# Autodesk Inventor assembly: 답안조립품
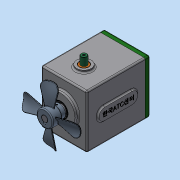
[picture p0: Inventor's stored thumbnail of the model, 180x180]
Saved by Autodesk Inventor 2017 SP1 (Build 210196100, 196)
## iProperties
Part Number: 답안조립품
Material: 일반
Document SubType Name: Assembly
Designer: MRC
Mass: 2669.46 g
Surface Area: 1952.93 cm^2
Volume: 798.897 cm^3
Density: 3.34143 g/cm^3
Author: MRC
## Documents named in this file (17)
- C:\Users\MRC\Desktop\610205V1002\답안조립품.iam
- C:\Users\MRC\Desktop\610205V1002\본체.ipt
- C:\Users\MRC\Desktop\610205V1002\멈춤나사 M3x8.ipt
- C:\Users\MRC\Desktop\610205V1002\메인 기어 축.ipt
- C:\Users\MRC\Desktop\610205V1002\베어링 608.ipt
- C:\Users\MRC\Desktop\610205V1002\베어링 6903.ipt
- C:\Users\MRC\Desktop\610205V1002\볼트 M4 x 10.ipt
- C:\Users\MRC\Desktop\610205V1002\부시.ipt
- C:\Users\MRC\Desktop\610205V1002\서브 기어 축.ipt
- C:\Users\MRC\Desktop\610205V1002\슬라이더.ipt
- C:\Users\MRC\Desktop\610205V1002\오일 실 8 22 7.ipt
- C:\Users\MRC\Desktop\610205V1002\오일 실 17 30 8.ipt
- C:\Users\MRC\Desktop\610205V1002\커버.ipt
- C:\Users\MRC\Desktop\610205V1002\키 5 x 5 x 24.ipt
- C:\Users\MRC\Desktop\610205V1002\팬날개.ipt
- 팬날개.ipt
- C:\Users\MRC\Desktop\610205V1002\가변스프링.ipt
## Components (1 placed, 1 different names)
1. 가변스프링:1
